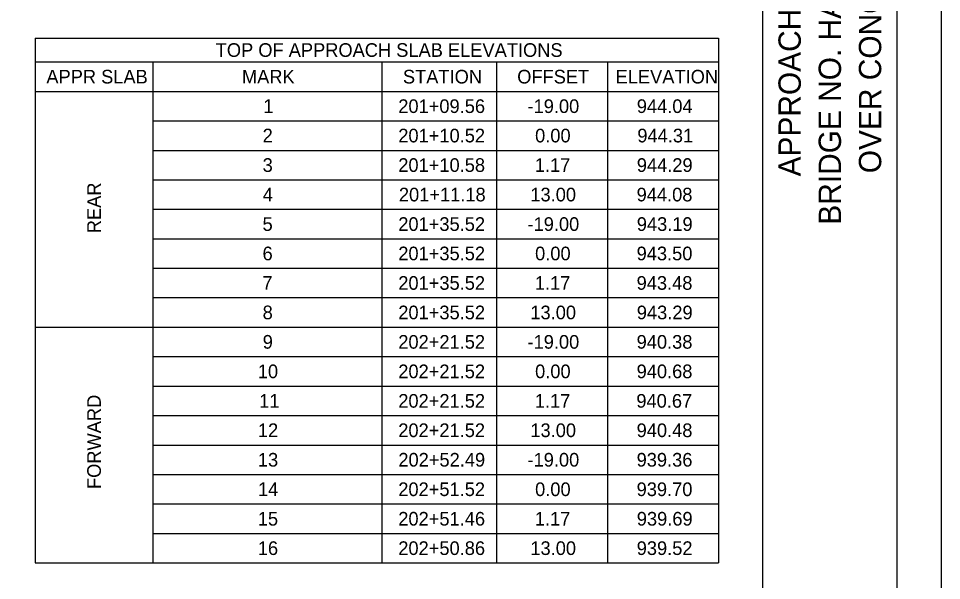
# Model space of a CAD drawing. Extents: x 0 to 34, y 0 to 22.
# Drawn here: x 23.67 to 34, y 6.98 to 13.27 of the extents above; entities that cross this region are included whole.
import ezdxf

# ---------------------------------------------------------------- set-up
doc = ezdxf.new("R2010")
doc.units = 0
for name, color, linetype in [('BR_P_Gen_Text', 7, 'Continuous'), ('SH_Border', 7, 'Continuous'), ('SH_Cut_Line', 7, 'Continuous'), ('SH_Data', 7, 'Continuous')]:
    doc.layers.add(name, color=color, linetype=linetype)

msp = doc.modelspace()

# ---------------------------------------------------------------- linework, layer by layer
at = {"layer": 'BR_P_Gen_Text'}
for p, q in [((23.857, 13.046), (31.504, 13.046)), ((23.857, 13.046), (23.857, 7.174)), ((31.504, 13.046), (31.504, 7.174)), ((23.857, 12.779), (31.504, 12.779)), ((25.176, 12.779), (25.176, 7.174)), ((27.738, 12.779), (27.738, 7.174)), ((29.019, 12.779), (29.019, 7.174)), ((30.261, 12.779), (30.261, 7.174)), ((23.857, 12.45), (31.504, 12.45)), ((25.176, 12.12), (31.504, 12.12)), ((25.176, 11.79), (31.504, 11.79)), ((25.176, 11.46), (31.504, 11.46)), ((25.176, 11.131), (31.504, 11.131)), ((25.176, 10.801), (31.504, 10.801)), ((25.176, 10.471), (31.504, 10.471)), ((25.176, 10.142), (31.504, 10.142)), ((23.857, 9.812), (31.504, 9.812)), ((25.176, 9.482), (31.504, 9.482)), ((25.176, 9.152), (31.504, 9.152)), ((25.176, 8.823), (31.504, 8.823)), ((25.176, 8.493), (31.504, 8.493)), ((25.176, 8.163), (31.504, 8.163)), ((25.176, 7.834), (31.504, 7.834)), ((25.176, 7.504), (31.504, 7.504)), ((23.857, 7.174), (31.504, 7.174))]:
    msp.add_line(p, q, dxfattribs=at)
at = {"layer": 'SH_Border'}
msp.add_line((32, 0.5), (32, 21.5), dxfattribs=at)
msp.add_lwpolyline([(1.5, 21.5), (33.5, 21.5), (33.5, 0.5), (1.5, 0.5)], close=True, dxfattribs=at)
at = {"layer": 'SH_Cut_Line'}
msp.add_lwpolyline([(0, 0), (34, 0), (34, 22), (0, 22)], close=True, dxfattribs=at)

# ---------------------------------------------------------------- texts
at = {"layer": 'BR_P_Gen_Text'}
for s, height, p in [('TOP OF APPROACH SLAB ELEVATIONS', 0.15273, (25.878, 12.836)), ('APPR SLAB', 0.1527, (23.983, 12.538)), ('MARK', 0.1527, (26.172, 12.538)), ('STATION', 0.1527, (27.973, 12.538)), ('OFFSET', 0.1527, (29.252, 12.538)), ('ELEVATION', 0.1527, (30.353, 12.538)), ('1', 0.153, (26.411, 12.208)), ('201+09.56', 0.1527, (27.921, 12.208)), ('-19.00', 0.1527, (29.367, 12.208)), ('944.04', 0.1527, (30.59, 12.208)), ('2', 0.153, (26.403, 11.879)), ('201+10.52', 0.1527, (27.921, 11.879)), ('0.00', 0.1527, (29.452, 11.879)), ('944.31', 0.1527, (30.596, 11.879)), ('3', 0.153, (26.403, 11.549)), ('201+10.58', 0.1527, (27.921, 11.549)), ('1.17', 0.1527, (29.449, 11.549)), ('944.29', 0.1527, (30.59, 11.549)), ('4', 0.153, (26.405, 11.219)), ('201+11.18', 0.1527, (27.928, 11.219)), ('13.00', 0.1527, (29.399, 11.219)), ('944.08', 0.1527, (30.588, 11.219)), ('5', 0.153, (26.402, 10.889)), ('201+35.52', 0.1527, (27.921, 10.889)), ('-19.00', 0.1527, (29.367, 10.889)), ('943.19', 0.1527, (30.59, 10.889)), ('6', 0.153, (26.402, 10.56)), ('201+35.52', 0.1527, (27.921, 10.56)), ('0.00', 0.1527, (29.452, 10.56)), ('943.50', 0.1527, (30.588, 10.56)), ('7', 0.153, (26.4, 10.23)), ('201+35.52', 0.1527, (27.921, 10.23)), ('1.17', 0.1527, (29.449, 10.23)), ('943.48', 0.1527, (30.588, 10.23)), ('8', 0.153, (26.403, 9.9)), ('201+35.52', 0.1527, (27.921, 9.9)), ('13.00', 0.1527, (29.399, 9.9)), ('943.29', 0.1527, (30.59, 9.9)), ('9', 0.153, (26.404, 9.571)), ('202+21.52', 0.1527, (27.921, 9.571)), ('-19.00', 0.1527, (29.367, 9.571)), ('940.38', 0.1527, (30.588, 9.571)), ('10', 0.1527, (26.349, 9.241)), ('202+21.52', 0.1527, (27.921, 9.241)), ('0.00', 0.1527, (29.452, 9.241)), ('940.68', 0.1527, (30.588, 9.241)), ('11', 0.1527, (26.365, 8.911)), ('202+21.52', 0.1527, (27.921, 8.911)), ('1.17', 0.1527, (29.449, 8.911)), ('940.67', 0.1527, (30.585, 8.911)), ('12', 0.1527, (26.35, 8.582)), ('202+21.52', 0.1527, (27.921, 8.582)), ('13.00', 0.1527, (29.399, 8.582)), ('940.48', 0.1527, (30.588, 8.582)), ('13', 0.1527, (26.35, 8.252)), ('202+52.49', 0.1527, (27.922, 8.252)), ('-19.00', 0.1527, (29.367, 8.252)), ('939.36', 0.1527, (30.588, 8.252)), ('14', 0.1527, (26.351, 7.922)), ('202+51.52', 0.1527, (27.921, 7.922)), ('0.00', 0.1527, (29.452, 7.922)), ('939.70', 0.1527, (30.588, 7.922)), ('202+51.46', 0.1527, (27.921, 7.592)), ('939.69', 0.1527, (30.59, 7.592)), ('15', 0.1527, (26.349, 7.592)), ('1.17', 0.1527, (29.449, 7.592)), ('16', 0.1527, (26.349, 7.263)), ('202+50.86', 0.1527, (27.921, 7.263)), ('13.00', 0.1527, (29.399, 7.263)), ('939.52', 0.1527, (30.589, 7.263))]:
    msp.add_text(s, height=height, dxfattribs=at).set_placement(p)
for s, p in [('REAR', (24.593, 10.863)), ('FORWARD', (24.593, 8.001))]:
    msp.add_text(s, height=0.1527, rotation=90, dxfattribs=at).set_placement(p)
at = {"layer": 'SH_Data'}
for s, p in [('BRIDGE NO. HAS-BRDGE-00.045', (32.875, 10.958)), ('APPROACH SLAB DETAILS', (32.425, 11.498)), ('OVER CONOTTON CREEK', (33.325, 11.534))]:
    msp.add_text(s, height=0.25, rotation=90, dxfattribs=at).set_placement(p)

doc.saveas('drawing.dxf')
